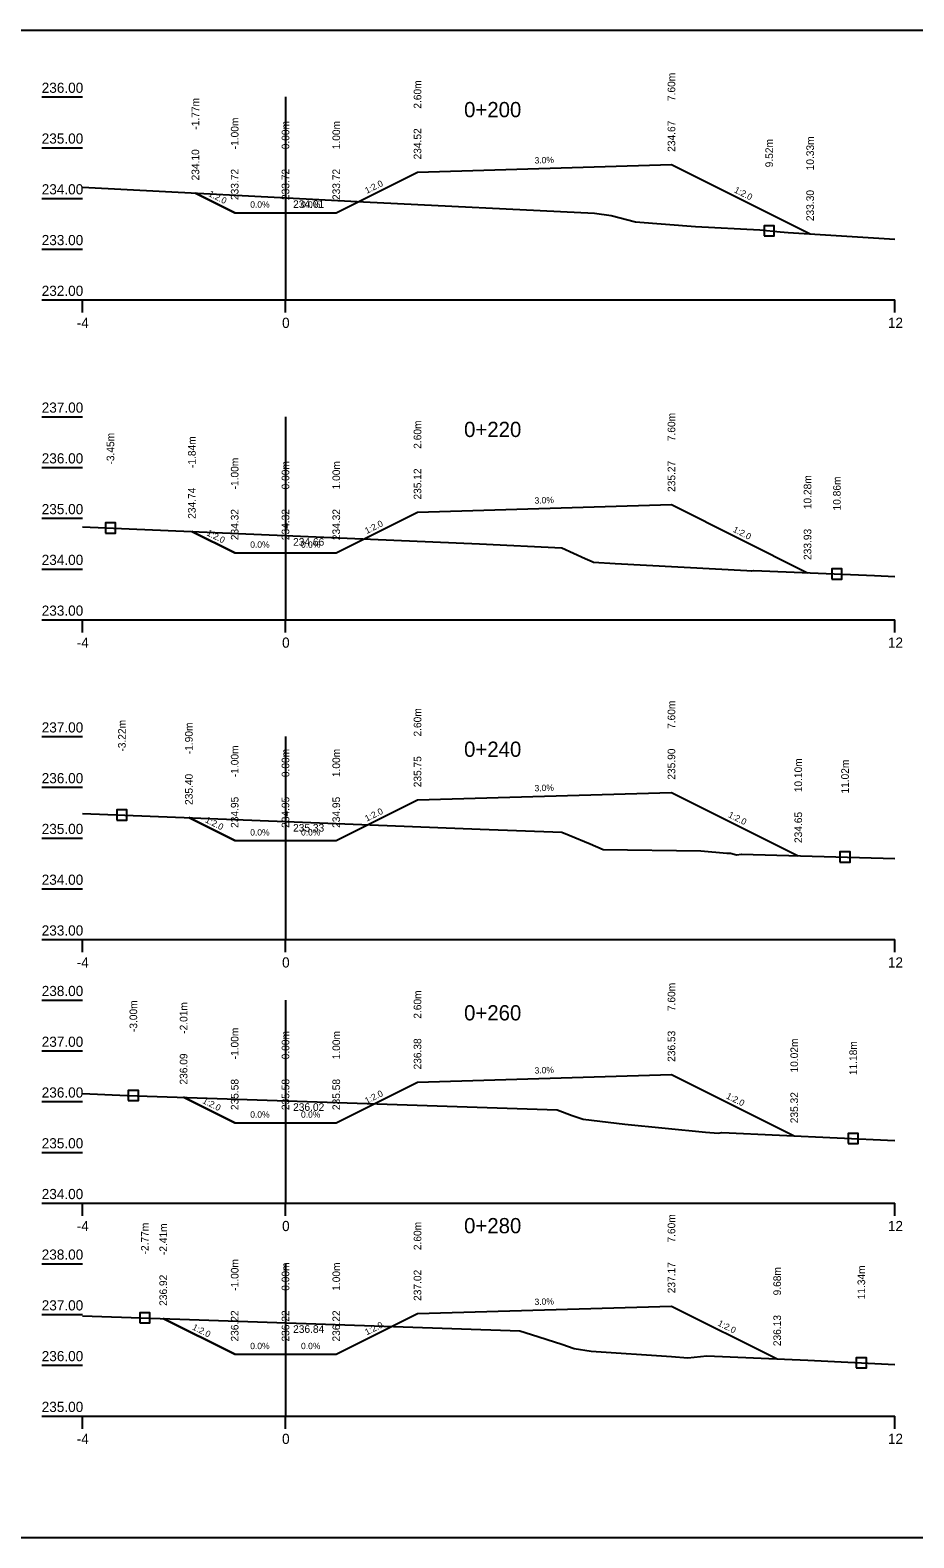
# Model space of a CAD drawing. Extents: x -578374 to -578229, y -1159997 to -1159967.
# Drawn here: x -578312.48 to -578295.08, y -1159996.88 to -1159967.18 of the extents above; entities that cross this region are included whole.
import ezdxf

# ---------------------------------------------------------------- set-up
doc = ezdxf.new("R2010")
doc.units = 0
for name, color, linetype in [('16', 7, 'Continuous'), ('21', 7, 'Continuous'), ('28', 7, 'Continuous'), ('59', 7, 'Continuous'), ('Body pricny rez', 7, 'Continuous'), ('Hranice_pozemku', 7, 'Continuous'), ('Popis pricneho profilu', 7, 'Continuous'), ('Rámy', 7, 'Continuous')]:
    doc.layers.add(name, color=color, linetype=linetype)

msp = doc.modelspace()

# ---------------------------------------------------------------- linework, layer by layer
for points in [[(-578309.231, -1159970.393), (-578308.457, -1159970.78), (-578307.457, -1159970.78), (-578306.457, -1159970.78), (-578304.857, -1159969.98), (-578299.857, -1159969.83), (-578297.126, -1159971.195)], [(-578306.457, -1159970.78), (-578304.857, -1159969.98), (-578299.857, -1159969.83)], [(-578299.857, -1159969.83), (-578297.126, -1159971.195)], [(-578311.457, -1159970.277), (-578305.92, -1159970.565), (-578301.371, -1159970.79), (-578301.046, -1159970.831), (-578300.565, -1159970.959), (-578299.381, -1159971.052), (-578298.114, -1159971.116), (-578297.716, -1159971.158), (-578297.56, -1159971.168), (-578295.457, -1159971.299)], [(-578308.457, -1159970.78), (-578309.231, -1159970.393)], [(-578308.457, -1159970.78), (-578307.457, -1159970.78), (-578306.457, -1159970.78)], [(-578297.126, -1159971.195), (-578297.127, -1159971.195), (-578297.126, -1159971.195), (-578297.127, -1159971.196), (-578297.126, -1159971.195), (-578297.126, -1159971.196), (-578297.126, -1159971.195), (-578297.126, -1159971.195)], [(-578309.3, -1159977.059), (-578308.457, -1159977.48), (-578307.457, -1159977.48), (-578306.457, -1159977.48), (-578304.857, -1159976.68), (-578299.857, -1159976.53), (-578297.177, -1159977.87)], [(-578306.457, -1159977.48), (-578304.857, -1159976.68), (-578299.857, -1159976.53)], [(-578299.857, -1159976.53), (-578297.177, -1159977.87)], [(-578311.457, -1159976.966), (-578303.635, -1159977.305), (-578302.015, -1159977.378), (-578301.553, -1159977.59), (-578301.42, -1159977.652), (-578301.404, -1159977.658), (-578301.395, -1159977.662), (-578300.968, -1159977.692), (-578298.375, -1159977.83), (-578298.284, -1159977.831), (-578298.279, -1159977.832), (-578298.234, -1159977.825), (-578295.86, -1159977.927), (-578295.457, -1159977.945)], [(-578308.457, -1159977.48), (-578309.3, -1159977.059)], [(-578308.457, -1159977.48), (-578307.457, -1159977.48), (-578306.457, -1159977.48)], [(-578297.177, -1159977.87), (-578297.178, -1159977.87), (-578297.177, -1159977.87), (-578297.178, -1159977.871), (-578297.177, -1159977.87), (-578297.177, -1159977.871), (-578297.177, -1159977.87), (-578297.177, -1159977.87)], [(-578309.359, -1159982.696), (-578308.457, -1159983.148), (-578307.457, -1159983.148), (-578306.457, -1159983.148), (-578304.857, -1159982.348), (-578299.857, -1159982.198), (-578297.36, -1159983.446)], [(-578306.457, -1159983.148), (-578304.857, -1159982.348), (-578299.857, -1159982.198)], [(-578299.857, -1159982.198), (-578297.36, -1159983.446)], [(-578311.457, -1159982.614), (-578303.625, -1159982.922), (-578302.016, -1159982.984), (-578301.871, -1159983.044), (-578301.459, -1159983.21), (-578301.204, -1159983.322), (-578299.277, -1159983.352), (-578298.764, -1159983.393), (-578298.694, -1159983.396), (-578298.573, -1159983.431), (-578298.477, -1159983.415), (-578295.457, -1159983.5)], [(-578308.457, -1159983.148), (-578309.359, -1159982.696)], [(-578308.457, -1159983.148), (-578307.457, -1159983.148), (-578306.457, -1159983.148)], [(-578297.36, -1159983.446), (-578297.36, -1159983.446), (-578297.36, -1159983.446), (-578297.36, -1159983.447), (-578297.36, -1159983.446), (-578297.359, -1159983.447), (-578297.36, -1159983.446), (-578297.359, -1159983.446)], [(-578309.463, -1159988.204), (-578308.457, -1159988.707), (-578307.457, -1159988.707), (-578306.457, -1159988.707), (-578304.857, -1159987.907), (-578299.857, -1159987.757), (-578297.439, -1159988.966)], [(-578306.457, -1159988.707), (-578304.857, -1159987.907), (-578299.857, -1159987.757)], [(-578299.857, -1159987.757), (-578297.439, -1159988.966)], [(-578311.457, -1159988.132), (-578310.573, -1159988.166), (-578302.109, -1159988.453), (-578301.811, -1159988.563), (-578301.592, -1159988.638), (-578300.777, -1159988.731), (-578299.184, -1159988.891), (-578298.933, -1159988.908), (-578298.866, -1159988.901), (-578295.457, -1159989.055)], [(-578308.457, -1159988.707), (-578309.463, -1159988.204)], [(-578308.457, -1159988.707), (-578307.457, -1159988.707), (-578306.457, -1159988.707)], [(-578297.439, -1159988.966), (-578297.44, -1159988.965), (-578297.439, -1159988.966), (-578297.44, -1159988.966), (-578297.439, -1159988.966), (-578297.439, -1159988.966), (-578297.439, -1159988.966), (-578297.439, -1159988.965)], [(-578311.457, -1159992.508), (-578302.842, -1159992.802), (-578302.612, -1159992.878), (-578302.013, -1159993.067), (-578301.771, -1159993.153), (-578301.437, -1159993.207), (-578299.856, -1159993.312), (-578299.537, -1159993.335), (-578299.157, -1159993.295), (-578297.169, -1159993.384), (-578295.457, -1159993.466)], [(-578309.864, -1159992.563), (-578308.457, -1159993.266), (-578307.457, -1159993.266), (-578306.457, -1159993.266), (-578304.857, -1159992.466), (-578299.857, -1159992.316), (-578297.775, -1159993.357)], [(-578308.457, -1159993.266), (-578309.864, -1159992.563)], [(-578306.457, -1159993.266), (-578304.857, -1159992.466), (-578299.857, -1159992.316)], [(-578299.857, -1159992.316), (-578297.775, -1159993.357)], [(-578308.457, -1159993.266), (-578307.457, -1159993.266), (-578306.457, -1159993.266)], [(-578297.775, -1159993.357), (-578297.776, -1159993.357), (-578297.775, -1159993.357), (-578297.776, -1159993.358), (-578297.775, -1159993.357), (-578297.775, -1159993.358), (-578297.775, -1159993.357), (-578297.775, -1159993.357)]]:
    msp.add_lwpolyline(points)
at = {"layer": '16'}
for p, q in [((-578311.457, -1159972.498), (-578295.457, -1159972.498)), ((-578311.457, -1159978.798), (-578295.457, -1159978.798)), ((-578311.457, -1159985.098), (-578295.457, -1159985.098)), ((-578311.457, -1159990.29), (-578295.457, -1159990.29)), ((-578311.457, -1159994.483), (-578295.457, -1159994.483))]:
    msp.add_line(p, q, dxfattribs=at)
at = {"layer": '21'}
for p, q in [((-578312.257, -1159968.498), (-578311.457, -1159968.498)), ((-578312.257, -1159969.498), (-578311.457, -1159969.498)), ((-578312.257, -1159970.498), (-578311.457, -1159970.498)), ((-578312.257, -1159971.498), (-578311.457, -1159971.498)), ((-578312.257, -1159972.498), (-578311.457, -1159972.498)), ((-578312.257, -1159974.798), (-578311.457, -1159974.798)), ((-578312.257, -1159975.798), (-578311.457, -1159975.798)), ((-578312.257, -1159976.798), (-578311.457, -1159976.798)), ((-578312.257, -1159977.798), (-578311.457, -1159977.798)), ((-578312.257, -1159978.798), (-578311.457, -1159978.798)), ((-578312.257, -1159981.098), (-578311.457, -1159981.098)), ((-578312.257, -1159982.098), (-578311.457, -1159982.098)), ((-578312.257, -1159983.098), (-578311.457, -1159983.098)), ((-578312.257, -1159984.098), (-578311.457, -1159984.098)), ((-578312.257, -1159985.098), (-578311.457, -1159985.098)), ((-578312.257, -1159986.29), (-578311.457, -1159986.29)), ((-578312.257, -1159987.29), (-578311.457, -1159987.29)), ((-578312.257, -1159988.29), (-578311.457, -1159988.29)), ((-578312.257, -1159989.29), (-578311.457, -1159989.29)), ((-578312.257, -1159990.29), (-578311.457, -1159990.29)), ((-578312.257, -1159991.483), (-578311.457, -1159991.483)), ((-578312.257, -1159992.483), (-578311.457, -1159992.483)), ((-578312.257, -1159993.483), (-578311.457, -1159993.483)), ((-578312.257, -1159994.483), (-578311.457, -1159994.483))]:
    msp.add_line(p, q, dxfattribs=at)
at = {"layer": '28'}
for p, q in [((-578307.457, -1159968.498), (-578307.457, -1159972.498)), ((-578307.457, -1159974.798), (-578307.457, -1159978.798)), ((-578307.457, -1159981.098), (-578307.457, -1159985.098)), ((-578307.457, -1159986.29), (-578307.457, -1159990.29)), ((-578307.457, -1159991.483), (-578307.457, -1159994.483))]:
    msp.add_line(p, q, dxfattribs=at)
at = {"layer": '59'}
for p, q in [((-578311.457, -1159972.748), (-578311.457, -1159972.498)), ((-578307.457, -1159972.748), (-578307.457, -1159972.498)), ((-578295.457, -1159972.748), (-578295.457, -1159972.498)), ((-578311.457, -1159979.048), (-578311.457, -1159978.798)), ((-578307.457, -1159979.048), (-578307.457, -1159978.798)), ((-578295.457, -1159979.048), (-578295.457, -1159978.798)), ((-578311.457, -1159985.348), (-578311.457, -1159985.098)), ((-578307.457, -1159985.348), (-578307.457, -1159985.098)), ((-578295.457, -1159985.348), (-578295.457, -1159985.098)), ((-578311.457, -1159990.54), (-578311.457, -1159990.29)), ((-578307.457, -1159990.54), (-578307.457, -1159990.29)), ((-578295.457, -1159990.54), (-578295.457, -1159990.29)), ((-578311.457, -1159994.733), (-578311.457, -1159994.483)), ((-578307.457, -1159994.733), (-578307.457, -1159994.483)), ((-578295.457, -1159994.733), (-578295.457, -1159994.483))]:
    msp.add_line(p, q, dxfattribs=at)
at = {"layer": 'Hranice_pozemku'}
for points in [[(-578298.032, -1159971.235), (-578297.832, -1159971.235), (-578297.832, -1159971.035), (-578298.032, -1159971.035)], [(-578311.004, -1159977.09), (-578310.804, -1159977.09), (-578310.804, -1159976.89), (-578311.004, -1159976.89)], [(-578296.699, -1159977.995), (-578296.499, -1159977.995), (-578296.499, -1159977.795), (-578296.699, -1159977.795)], [(-578310.778, -1159982.745), (-578310.578, -1159982.745), (-578310.578, -1159982.545), (-578310.778, -1159982.545)], [(-578296.539, -1159983.572), (-578296.339, -1159983.572), (-578296.339, -1159983.372), (-578296.539, -1159983.372)], [(-578310.552, -1159988.27), (-578310.352, -1159988.27), (-578310.352, -1159988.07), (-578310.552, -1159988.07)], [(-578296.378, -1159989.118), (-578296.178, -1159989.118), (-578296.178, -1159988.918), (-578296.378, -1159988.918)], [(-578310.326, -1159992.65), (-578310.126, -1159992.65), (-578310.126, -1159992.45), (-578310.326, -1159992.45)], [(-578296.218, -1159993.535), (-578296.018, -1159993.535), (-578296.018, -1159993.335), (-578296.218, -1159993.335)]]:
    msp.add_lwpolyline(points, close=True, dxfattribs=at)
at = {"layer": 'Rámy'}
msp.add_lwpolyline([(-578373.807, -1159967.183), (-578228.93, -1159967.183), (-578228.93, -1159996.883), (-578373.807, -1159996.883)], close=True, dxfattribs=at)

# ---------------------------------------------------------------- texts
for s, height, p in [('0+200', 0.3, (-578303.94, -1159968.898)), ('+', 0.001, (-578307.458, -1159970.78)), ('0+220', 0.3, (-578303.94, -1159975.198)), ('+', 0.001, (-578307.458, -1159977.481)), ('0+240', 0.3, (-578303.94, -1159981.498)), ('+', 0.001, (-578307.458, -1159983.148)), ('0+260', 0.3, (-578303.94, -1159986.69)), ('+', 0.001, (-578307.458, -1159988.707)), ('0+280', 0.3, (-578303.94, -1159990.883)), ('+', 0.001, (-578307.458, -1159993.267))]:
    msp.add_text(s, height=height).set_placement(p)
for rotation, p in [(26.5651, (-578305.855, -1159970.409)), (333.4349, (-578298.634, -1159970.372)), (333.4349, (-578308.986, -1159970.446)), (26.5651, (-578305.855, -1159977.11)), (333.4349, (-578309.02, -1159977.129)), (333.4349, (-578298.659, -1159977.06)), (333.4349, (-578309.05, -1159982.781)), (26.5651, (-578305.855, -1159982.777)), (333.4349, (-578298.75, -1159982.681)), (26.5651, (-578305.855, -1159988.336)), (333.4349, (-578298.79, -1159988.22)), (333.4349, (-578309.102, -1159988.314)), (333.4349, (-578309.303, -1159992.774)), (26.5651, (-578305.855, -1159992.895)), (333.4349, (-578298.958, -1159992.696))]:
    msp.add_text('1:2.0', height=0.125, rotation=rotation).set_placement(p)
at = {"layer": '16'}
for s, rotation, p in [('3.0%', 1.7184, (-578302.551, -1159969.811)), ('0.0%', 360, (-578308.151, -1159970.68)), ('0.0%', 360, (-578307.151, -1159970.68)), ('3.0%', 1.7184, (-578302.551, -1159976.511)), ('0.0%', 360, (-578308.151, -1159977.38)), ('0.0%', 360, (-578307.151, -1159977.38)), ('3.0%', 1.7184, (-578302.551, -1159982.178)), ('0.0%', 360, (-578308.151, -1159983.048)), ('0.0%', 360, (-578307.151, -1159983.048)), ('3.0%', 1.7184, (-578302.551, -1159987.738)), ('0.0%', 360, (-578308.151, -1159988.607)), ('0.0%', 360, (-578307.151, -1159988.607)), ('3.0%', 1.7184, (-578302.551, -1159992.297)), ('0.0%', 360, (-578308.151, -1159993.166)), ('0.0%', 360, (-578307.151, -1159993.166))]:
    msp.add_text(s, height=0.125, rotation=rotation, dxfattribs=at).set_placement(p)
at = {"layer": '21'}
for s, p in [('236.00', (-578312.257, -1159968.418)), ('235.00', (-578312.257, -1159969.418)), ('234.00', (-578312.257, -1159970.418)), ('233.00', (-578312.257, -1159971.418)), ('232.00', (-578312.257, -1159972.418)), ('-4', (-578311.567, -1159973.048)), ('0', (-578307.524, -1159973.048)), ('12', (-578295.595, -1159973.048)), ('237.00', (-578312.257, -1159974.718)), ('236.00', (-578312.257, -1159975.718)), ('235.00', (-578312.257, -1159976.718)), ('234.00', (-578312.257, -1159977.718)), ('233.00', (-578312.257, -1159978.718)), ('-4', (-578311.567, -1159979.348)), ('0', (-578307.524, -1159979.348)), ('12', (-578295.595, -1159979.348)), ('237.00', (-578312.257, -1159981.018)), ('236.00', (-578312.257, -1159982.018)), ('235.00', (-578312.257, -1159983.018)), ('234.00', (-578312.257, -1159984.018)), ('233.00', (-578312.257, -1159985.018)), ('-4', (-578311.567, -1159985.648)), ('0', (-578307.524, -1159985.648)), ('12', (-578295.595, -1159985.648)), ('238.00', (-578312.257, -1159986.21)), ('237.00', (-578312.257, -1159987.21)), ('236.00', (-578312.257, -1159988.21)), ('235.00', (-578312.257, -1159989.21)), ('234.00', (-578312.257, -1159990.21)), ('-4', (-578311.567, -1159990.84)), ('0', (-578307.524, -1159990.84)), ('12', (-578295.595, -1159990.84)), ('238.00', (-578312.257, -1159991.403)), ('237.00', (-578312.257, -1159992.403)), ('236.00', (-578312.257, -1159993.403)), ('235.00', (-578312.257, -1159994.403)), ('-4', (-578311.567, -1159995.033)), ('0', (-578307.524, -1159995.033)), ('12', (-578295.595, -1159995.033))]:
    msp.add_text(s, height=0.2, dxfattribs=at).set_placement(p)
at = {"layer": '59'}
for s, p in [('234.01', (-578307.307, -1159970.685)), ('234.66', (-578307.307, -1159977.339)), ('235.33', (-578307.307, -1159982.971)), ('236.02', (-578307.307, -1159988.472)), ('236.84', (-578307.307, -1159992.845))]:
    msp.add_text(s, height=0.15, dxfattribs=at).set_placement(p)
at = {"layer": 'Body pricny rez'}
for p in [(-578304.858, -1159969.98), (-578299.858, -1159969.83), (-578309.231, -1159970.394), (-578308.458, -1159970.78), (-578306.458, -1159970.78), (-578299.858, -1159976.531), (-578304.858, -1159976.681), (-578309.3, -1159977.06), (-578308.458, -1159977.481), (-578306.458, -1159977.481), (-578299.858, -1159982.198), (-578304.858, -1159982.348), (-578309.36, -1159982.697), (-578308.458, -1159983.148), (-578306.458, -1159983.148), (-578299.858, -1159987.757), (-578304.858, -1159987.907), (-578309.464, -1159988.204), (-578308.458, -1159988.707), (-578306.458, -1159988.707), (-578309.865, -1159992.563), (-578304.858, -1159992.467), (-578299.858, -1159992.317), (-578308.458, -1159993.267), (-578306.458, -1159993.267)]:
    msp.add_text('+', height=0.001, dxfattribs=at).set_placement(p)
at = {"layer": 'Popis pricneho profilu'}
for s, p in [('2.60m', (-578304.782, -1159968.73)), ('7.60m', (-578299.782, -1159968.58)), ('-1.77m', (-578309.156, -1159969.143)), ('-1.00m', (-578308.382, -1159969.53)), ('0.00m', (-578307.382, -1159969.53)), ('1.00m', (-578306.382, -1159969.53)), ('234.52', (-578304.782, -1159969.73)), ('234.67', (-578299.782, -1159969.58)), ('9.52m', (-578297.857, -1159969.885)), ('10.33m', (-578297.051, -1159969.945)), ('234.10', (-578309.156, -1159970.143)), ('233.72', (-578308.382, -1159970.53)), ('233.72', (-578307.382, -1159970.53)), ('233.72', (-578306.382, -1159970.53)), ('233.30', (-578297.051, -1159970.945)), ('7.60m', (-578299.782, -1159975.28)), ('2.60m', (-578304.782, -1159975.43)), ('-3.45m', (-578310.829, -1159975.74)), ('-1.84m', (-578309.225, -1159975.809)), ('-1.00m', (-578308.382, -1159976.23)), ('0.00m', (-578307.382, -1159976.23)), ('1.00m', (-578306.382, -1159976.23)), ('235.12', (-578304.782, -1159976.43)), ('235.27', (-578299.782, -1159976.28)), ('10.28m', (-578297.102, -1159976.62)), ('234.74', (-578309.225, -1159976.809)), ('10.86m', (-578296.524, -1159976.645)), ('234.32', (-578308.382, -1159977.23)), ('234.32', (-578307.382, -1159977.23)), ('234.32', (-578306.382, -1159977.23)), ('233.93', (-578297.102, -1159977.62)), ('7.60m', (-578299.782, -1159980.948)), ('2.60m', (-578304.782, -1159981.098)), ('-3.22m', (-578310.603, -1159981.395)), ('-1.90m', (-578309.284, -1159981.446)), ('-1.00m', (-578308.382, -1159981.898)), ('0.00m', (-578307.382, -1159981.898)), ('1.00m', (-578306.382, -1159981.898)), ('235.75', (-578304.782, -1159982.098)), ('235.90', (-578299.782, -1159981.948)), ('10.10m', (-578297.285, -1159982.196)), ('11.02m', (-578296.364, -1159982.222)), ('235.40', (-578309.284, -1159982.446)), ('234.95', (-578308.382, -1159982.898)), ('234.95', (-578307.382, -1159982.898)), ('234.95', (-578306.382, -1159982.898)), ('234.65', (-578297.285, -1159983.196)), ('7.60m', (-578299.782, -1159986.507)), ('-3.00m', (-578310.377, -1159986.92)), ('-2.01m', (-578309.388, -1159986.954)), ('2.60m', (-578304.782, -1159986.657)), ('-1.00m', (-578308.382, -1159987.457)), ('0.00m', (-578307.382, -1159987.457)), ('1.00m', (-578306.382, -1159987.457)), ('236.53', (-578299.782, -1159987.507)), ('236.38', (-578304.782, -1159987.657)), ('10.02m', (-578297.364, -1159987.716)), ('11.18m', (-578296.203, -1159987.768)), ('236.09', (-578309.388, -1159987.954)), ('235.58', (-578308.382, -1159988.457)), ('235.58', (-578307.382, -1159988.457)), ('235.58', (-578306.382, -1159988.457)), ('235.32', (-578297.364, -1159988.716)), ('7.60m', (-578299.782, -1159991.066)), ('-2.77m', (-578310.151, -1159991.3)), ('-2.41m', (-578309.789, -1159991.313)), ('2.60m', (-578304.782, -1159991.216)), ('-1.00m', (-578308.382, -1159992.016)), ('236.92', (-578309.789, -1159992.313)), ('0.00m', (-578307.382, -1159992.016)), ('1.00m', (-578306.382, -1159992.016)), ('237.02', (-578304.782, -1159992.216)), ('237.17', (-578299.782, -1159992.066)), ('9.68m', (-578297.7, -1159992.107)), ('11.34m', (-578296.043, -1159992.185)), ('236.22', (-578308.382, -1159993.016)), ('236.22', (-578307.382, -1159993.016)), ('236.22', (-578306.382, -1159993.016)), ('236.13', (-578297.7, -1159993.107))]:
    msp.add_text(s, height=0.15, rotation=90, dxfattribs=at).set_placement(p)

doc.saveas('drawing.dxf')
